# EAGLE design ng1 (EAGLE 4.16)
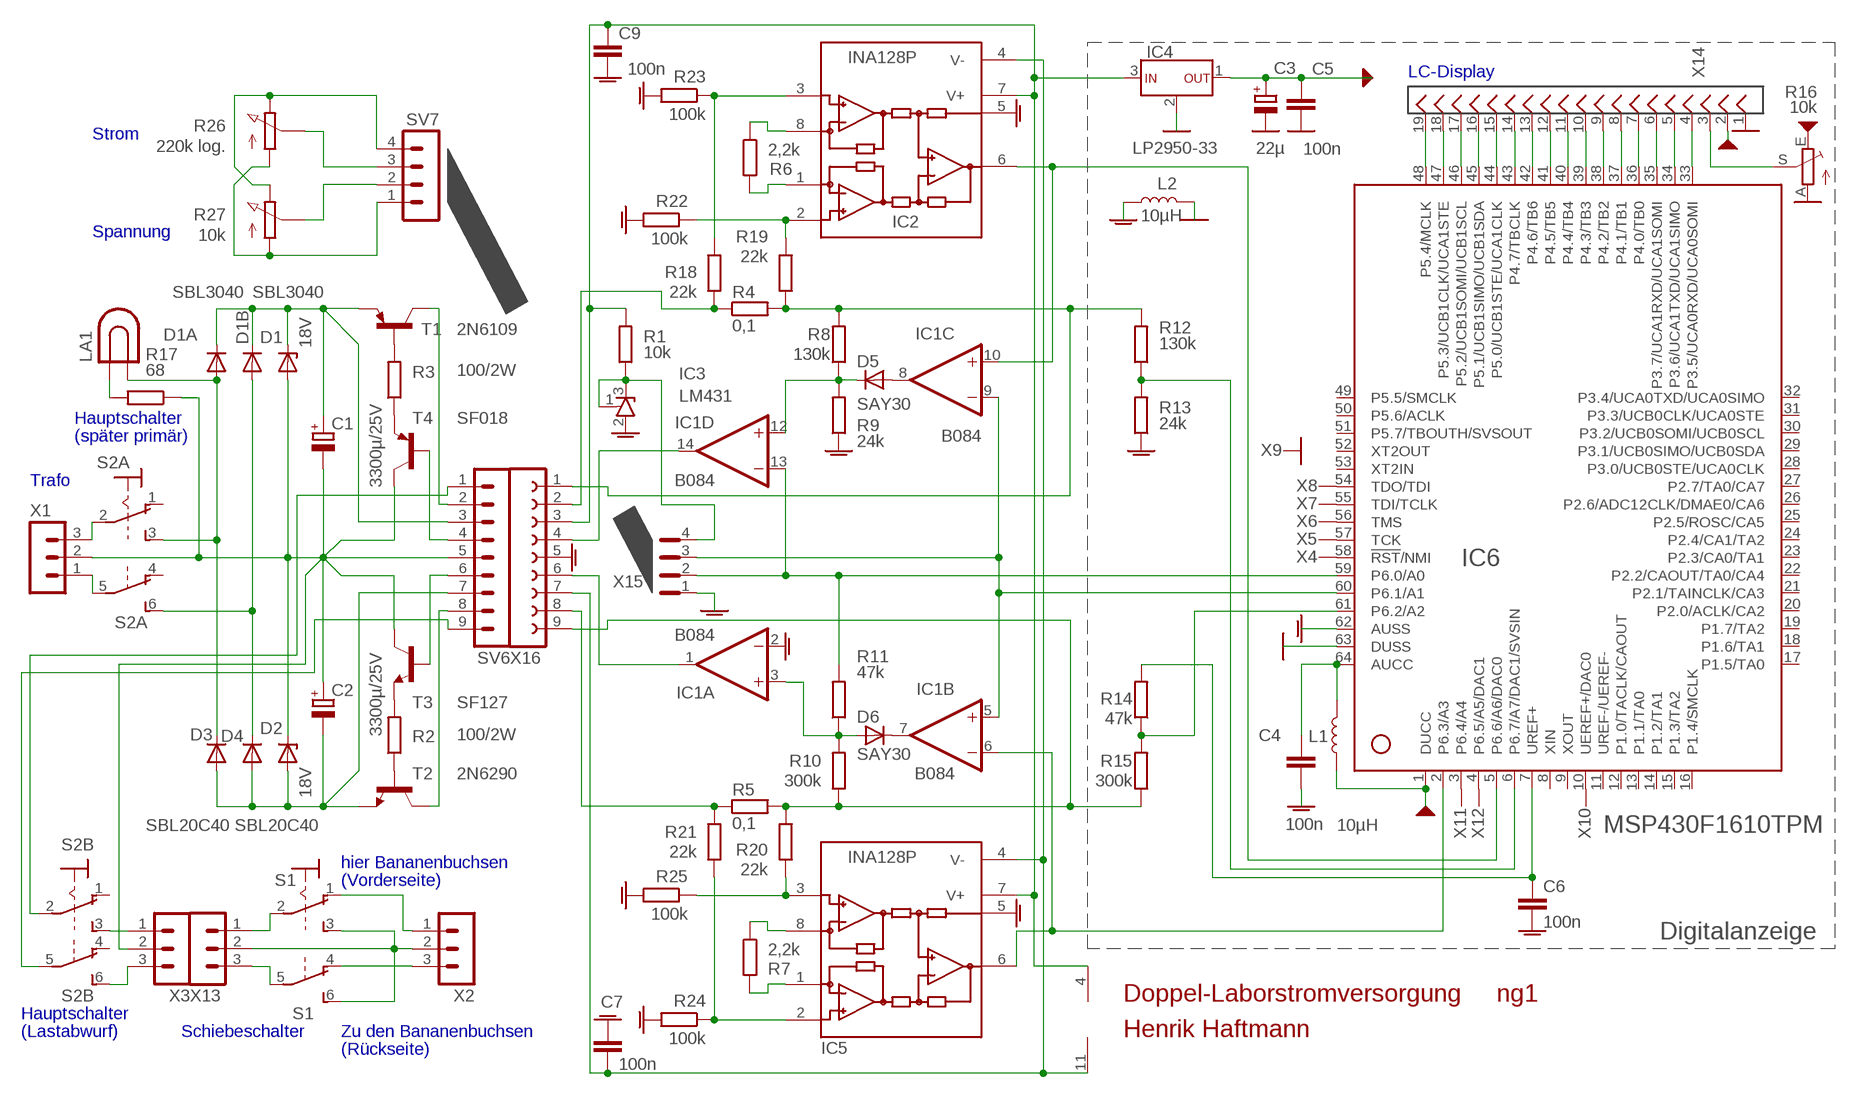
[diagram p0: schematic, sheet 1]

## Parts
C1  3300µ/25V  CPOL-EUE7.5-16  [E7,5-16]
C2  3300µ/25V  CPOL-EUE7.5-16  [E7,5-16]
C3  22µ  CPOL-EUE2-5  [E2-5]
C4  100n  C  [0603]
C5  100n  C  [0603]
C6  100n  C  [0603]
C7  100n  C-EU050-025X075  [C050-025X075]
C9  100n  C-EU050-025X075  [C050-025X075]
D1  18V  ZENER-DIODEC1702-15  [C1702-15]
D1A  SBL3040  DIODE  [DO202-17]
D1B  SBL3040  DIODE  [DO202-17]
D2  18V  ZENER-DIODEC1702-15  [C1702-15]
D3  SBL20C40  DIODE  [DO202-17]
D4  SBL20C40  DIODE  [DO202-17]
D5  SAY30  DD  [SAY]
D6  SAY30  DD  [SAY]
IC1  B084  TL084P  [DIL14]
IC2  INA128P  [DIL08]
IC3  LM431  TL431  [TO-92]
IC4  LP2950-33  78L05  [TO-92]
IC5  INA128P  [DIL08]
IC6  MSP430F1610TPM  MSP430F261TPM  [LQFP-64]
L1  10µH  L  [0603]
L2  10µH  L  [0603]
LA1  LAMP  [LDH-5R]
R1  10k  R-EU_0207/10  [0207/10]
R2  100/2W  R-EU_0617/22  [0617/22]
R3  100/2W  R-EU_0617/22  [0617/22]
R4  0,1  R-EU_0309/12  [0309/12]
R5  0,1  R-EU_0309/12  [0309/12]
R6  2,2k  R-EU_0207/10  [0207/10]
R7  2,2k  R-EU_0207/10  [0207/10]
R8  130k  R-EU_0207/10  [0207/10]
R9  24k  R-EU_0207/10  [0207/10]
R10  300k  R-EU_0207/10  [0207/10]
R11  47k  R-EU_0207/10  [0207/10]
R12  130k  R-EU_0207/10  [0207/10]
R13  24k  R-EU_0207/10  [0207/10]
R14  47k  R-EU_0207/10  [0207/10]
R15  300k  R-EU_0207/10  [0207/10]
R16  10k  TRIM_EU-CA9V  [CA9V]
R17  68  R-EU_0207/10  [0207/10]
R18  22k  R-EU_0207/10  [0207/10]
R19  22k  R-EU_0207/10  [0207/10]
R20  22k  R-EU_0207/10  [0207/10]
R21  22k  R-EU_0207/10  [0207/10]
R22  100k  R-EU_0207/10  [0207/10]
R23  100k  R-EU_0207/10  [0207/10]
R24  100k  R-EU_0207/10  [0207/10]
R25  100k  R-EU_0207/10  [0207/10]
R26  220k log.  PC25  [PC25]
R27  10k  PC25  [PC25]
S1  320-938  [320-938]
S2A  320-938  [320-938]
S2B  320-938  [320-938]
SV6  MA09-1  [MA09-1]
SV7  MA04-1  [MA04-1]
T1  2N6109  -PNP-TO220V  [TO220V]
T2  2N6290  -NPN-TO220V  [TO220V]
T3  SF127  -NPN-TO5  [TO5]
T4  SF018  -PNP-TO5  [TO5]
X1  MA03-1  [MA03-1]
X2  MA03-1  [MA03-1]
X3  MA03-1  [MA03-1]
X4  PADM  [SMD-1MM5]
X5  PADM  [SMD-1MM5]
X6  PADM  [SMD-1MM5]
X7  PADM  [SMD-1MM5]
X8  PADM  [SMD-1MM5]
X9  PADM  [SMD-1MM5]
X10  PADM  [SMD-1MM5]
X11  PADM  [SMD-1MM5]
X12  PADM  [SMD-1MM5]
X13  MA03-1  [MA03-1]
X14  FFC19  [FFC19]
X15  M4  [M4]
X16  FE09-1  [FE09]

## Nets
3P3: C3.+ C5.1 IC4.1(OUT) IC6.1(DUCC) L1.1 R16.E X14.2
15N: R5.2 R10.1 R15.1 R20.2 X16.9
15P: R4.2 R8.2 R12.2 R19.1 X16.1
18N: C7.2 IC1.11(P:V-) IC2.4(V-) IC5.4(V-) X16.7
18N1: C2.- D2.A D3.A D4.A SV6.7 T2.3(E)
18P: C9.1 IC1.4(P:V+) IC2.7(V+) IC4.3(IN) IC5.7(V+) R1.2 X16.3
18P1: C1.+ D1.C D1A.C D1B.C SV6.3 T1.3(E)
AGND: C4.2 C6.2 C7.1 C9.2 IC1.2(A:-IN) IC2.5(REF) IC3.2(A) IC5.5(REF) IC6.62(AUSS) L2.2 R9.1 R13.1 R22.2 R23.2 R24.2 R25.2 X15.1 X16.5
GND: C3.- C5.2 IC4.2(GND) IC6.63(DUSS) L2.1 R16.A X9.1 X14.1
GND1: C1.- C2.+ D1.A D2.C R17.1 SV6.5 T3.3(C) T4.3(C) X1.2 X3.2
N$1: D1A.A D3.C LA1.2 S2A.3(1:S)
N$2: D1B.A D4.C S2A.6(B:S)
N$3: IC6.46(P5.2/UCB1SOMI/UCB1SCL) X14.17
N$4: IC6.47(P5.3/UCB1CLK/UCA1STE) X14.18
N$5: IC6.48(P5.4/MCLK) X14.19
N$6: R2.1 T2.1(B)
N$7: R3.2 T1.1(B)
N$8: R3.1 T4.1(E)
N$9: R2.2 T3.1(E)
N$10: IC3.1(R) IC3.3(C) R1.1 X15.4
N$11: IC6.3(P6.4/A4) X11.1
N$12: R4.1 R18.1 X16.2
N$13: R5.1 R21.2 X16.8
N$14: IC6.4(P6.5/A5/DAC1) X12.1
N$15: IC2.8(RG) R6.1
N$16: IC2.1(RG) R6.2
N$17: LA1.1 R17.2
N$18: IC5.1(RG) R7.2
N$19: IC5.8(RG) R7.1
N$20: S2A.2(1:P) X1.3
N$22: D5.K IC1.12(D:+IN) R8.1 R9.2
N$23: D5.A IC1.8(C:OUT)
N$24: IC1.13(D:-IN) IC6.59(P6.0/A0) R11.2 X15.2
N$25: D6.A IC1.3(A:+IN) R10.2 R11.1
N$26: IC1.6(B:-IN) IC5.6(OUT) IC6.2(P6.3/A3)
N$27: IC1.10(C:+IN) IC2.6(OUT) IC6.5(P6.6/A6/DAC0)
N$28: IC1.5(B:+IN) IC1.9(C:-IN) IC6.60(P6.1/A1) X15.3
N$29: D6.K IC1.7(B:OUT)
N$30: IC6.6(P6.7/A7/DAC1/SVSIN) R12.1 R13.2
N$31: IC6.61(P6.2/A2) R14.1 R15.2
N$32: IC6.43(P4.7/TBCLK) X14.14
N$33: IC6.42(P4.6/TB6) X14.13
N$34: IC6.41(P4.5/TB5) X14.12
N$35: IC6.40(P4.4/TB4) X14.11
N$36: IC6.39(P4.3/TB3) X14.10
N$37: IC6.38(P4.2/TB2) X14.9
N$38: IC6.37(P4.1/TB1) X14.8
N$39: IC6.58(!RST!/NMI) X4.1
N$40: IC6.57(TCK) X5.1
N$41: IC6.56(TMS) X6.1
N$42: IC6.54(TDO/TDI) X8.1
N$43: IC6.55(TDI/TCLK) X7.1
N$44: C4.1 IC6.64(AUCC) L1.2
N$45: R16.S X14.3
N$46: IC6.10(UEREF+/DAC0) X10.1
N$49: C6.1 IC6.7(UREF+) R14.2
N$50: IC5.3(+IN) R20.1 R25.1
N$51: IC2.2(-IN) R19.2 R22.1
N$52: IC2.3(+IN) R18.2 R23.1
N$53: IC5.2(-IN) R21.1 R24.1
N$54: S2A.5(B:P) X1.1
N$55: SV6.6 T3.2(B)
N$56: SV6.4 T4.2(B)
N$57: SV6.8 T2.2(C)
N$58: SV6.2 T1.2(C)
N$59: IC1.14(D:OUT) X16.4
N$60: IC1.1(A:OUT) X16.6
N$61: R26.E R27.E SV7.4
N$62: R26.S SV7.3
N$63: R27.S SV7.2
N$64: R26.A R27.A SV7.1
N$65: S1.2(1:P) X13.1
N$66: S2B.3(1:S) X3.1
N$67: S1.3(1:S) S1.6(B:S) X2.2 X13.2
N$68: S1.1(1:O) X2.1
N$69: S1.4(B:O) X2.3
N$70: S1.5(B:P) X13.3
N$71: S2B.6(B:S) X3.3
N$72: S2B.2(1:P) SV6.1
N$73: S2B.5(B:P) SV6.9
N$74: IC6.36(P4.0/TB0) X14.7
N$75: IC6.35(P3.7/UCA1RXD/UCA1SOMI) X14.6
N$76: IC6.34(P3.6/UCA1TXD/UCA1SIMO) X14.5
N$77: IC6.33(P3.5/UCA0RXD/UCA0SOMI) X14.4
N$79: IC6.44(P5.0/UCB1STE/UCA1CLK) X14.15
N$80: IC6.45(P5.1/UCB1SIMO/UCB1SDA) X14.16
Unconnected: IC6.8(XIN) IC6.9(XOUT) IC6.11(UREF-/UEREF-) IC6.12(P1.0/TACLK/CAOUT) IC6.13(P1.1/TA0) IC6.14(P1.2/TA1) IC6.15(P1.3/TA2) IC6.16(P1.4/SMCLK) IC6.17(P1.5/TA0) IC6.18(P1.6/TA1) IC6.19(P1.7/TA2) IC6.20(P2.0/ACLK/CA2) IC6.21(P2.1/TAINCLK/CA3) IC6.22(P2.2/CAOUT/TA0/CA4) IC6.23(P2.3/CA0/TA1) IC6.24(P2.4/CA1/TA2) IC6.25(P2.5/ROSC/CA5) IC6.26(P2.6/ADC12CLK/DMAE0/CA6) IC6.27(P2.7/TA0/CA7) IC6.28(P3.0/UCB0STE/UCA0CLK) IC6.29(P3.1/UCB0SIMO/UCB0SDA) IC6.30(P3.2/UCB0SOMI/UCB0SCL) IC6.31(P3.3/UCB0CLK/UCA0STE) IC6.32(P3.4/UCA0TXD/UCA0SIMO) IC6.49(P5.5/SMCLK) IC6.50(P5.6/ACLK) IC6.51(P5.7/TBOUTH/SVSOUT) IC6.52(XT2OUT) IC6.53(XT2IN) S2A.1(1:O) S2A.4(B:O) S2B.1(1:O) S2B.4(B:O)

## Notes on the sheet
- LC-Display
- Strom
- Spannung
- Hauptschalter
- (später primär)
- Trafo
- hier Bananenbuchsen
- (Vorderseite)
- Digitalanzeige
- Doppel-Laborstromversorgung
- Hauptschalter
- (Lastabwurf) | Schiebeschalter | Zu den Bananenbuchsen | Henrik Haftmann
- (Rückseite)

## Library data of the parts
C1-C3 = rcl:CPOL-EU: POLARIZED CAPACITOR, European symbol
C4-C6 = sm:C: Kondensator
C7 C9 = rcl:C-EU: CAPACITOR, European symbol
D1 D2 = diode:ZENER-DIODE: Z-Diode
D1A D1B D3 D4 = lm:DIODE: Diode
D5 D6 = sm:D: Diode
IC1 = linear:TL084: OP AMP
IC2 IC5 = burr-brown:INA128: Instrumentation Amplifiers Precision, Low Power
IC3 = lm:TL431*: Einstellbare Z-Diode Umin = 2,5 V
IC4 = lm:78L*: Spannungsregler
IC6 = sm:MSP430F261*TPM: Microcontroller 16 bit RISC 1.8 .. 3.6 V 16 MHz Low-Power 365 µA @ 1 MHz & 2.2 V, 0.5 µA Standby, 0.1 A Off, Wake-Up: 1 µs 40 I/O pins 3-channel DMA, 2 12-bit DAC (261x only) 1 12-bit ADC 2 16-bit timers with 3+7 capture/compare registers 4 universal serial interfaces (RS232, I²C, SPI, ...)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
L1 L2 = sm:L: Spule (Hochfrequenz)
LA1 = special:LAMP: LED HOLDER
R1-R15 R17-R25 = rcl:R-EU_: RESISTOR, European symbol
R16 = pot:TRIM_EU-: POTENTIOMETER
R26 R27 = pot-vitrohm:PC25: VITROHM POTENTIOMETER
S1 S2A S2B = switch:320-938: TOGGLE SWITCH distributor RS Components
SV6 = con-lstb:MA09-1: PIN HEADER
SV7 = con-lstb:MA04-1: PIN HEADER
T1 T4 = transistor:*-PNP-: PNP Transistror
T2 T3 = transistor:*-NPN-: NPN Transistror
X1-X3 X13 = con-lstb:MA03-1: PIN HEADER
X4-X12 = sm:PAD: Einfaches Lötpad
X14 = lm:FFC19: Flachkabel-Verbinder 19-polig
X15 = lm:M4: Stecker 4-pol.
X16 = con-lsta:FE09-1: FEMALE HEADER

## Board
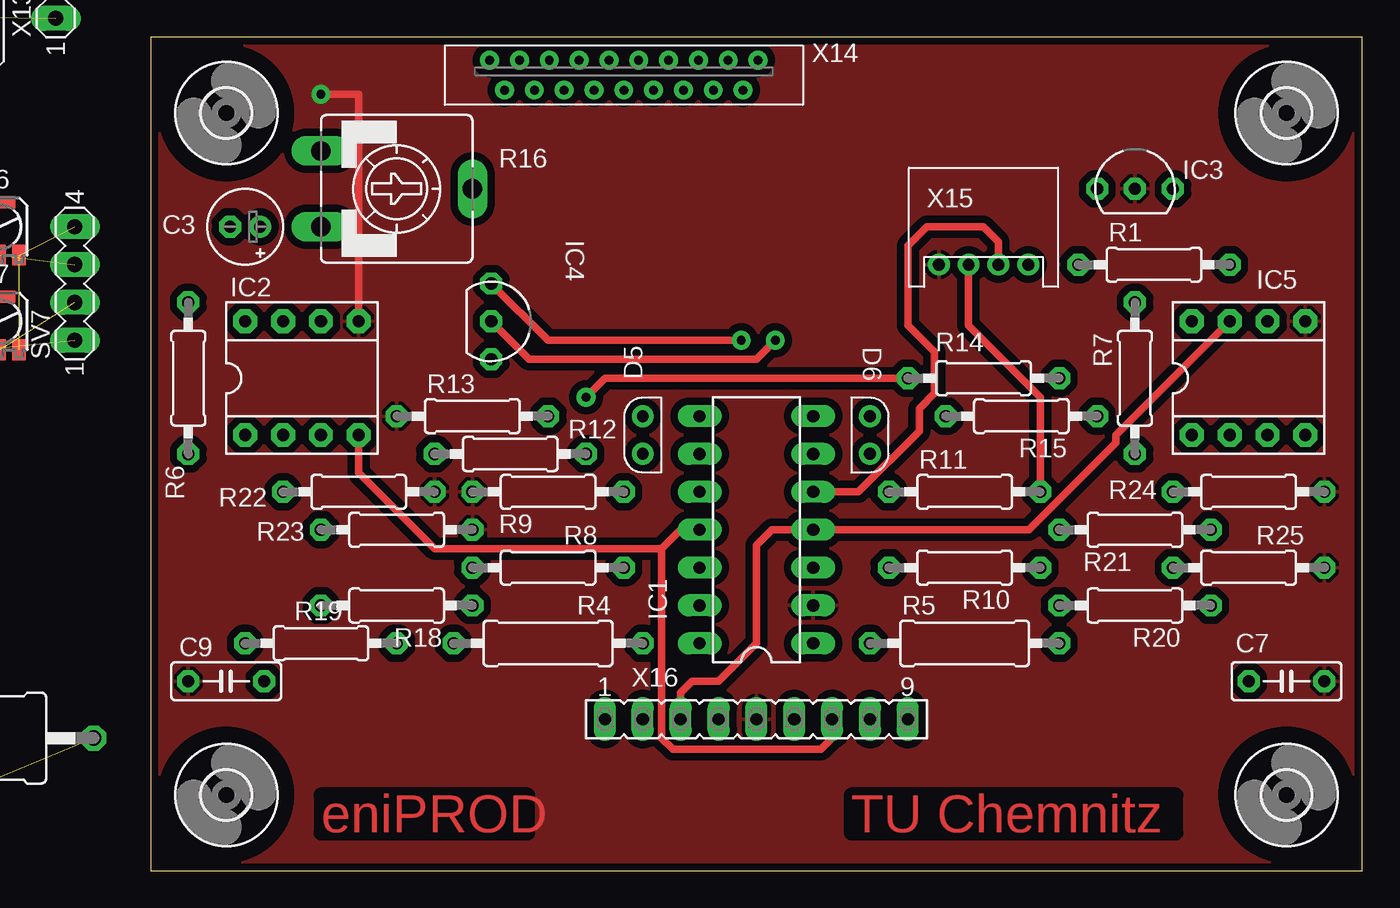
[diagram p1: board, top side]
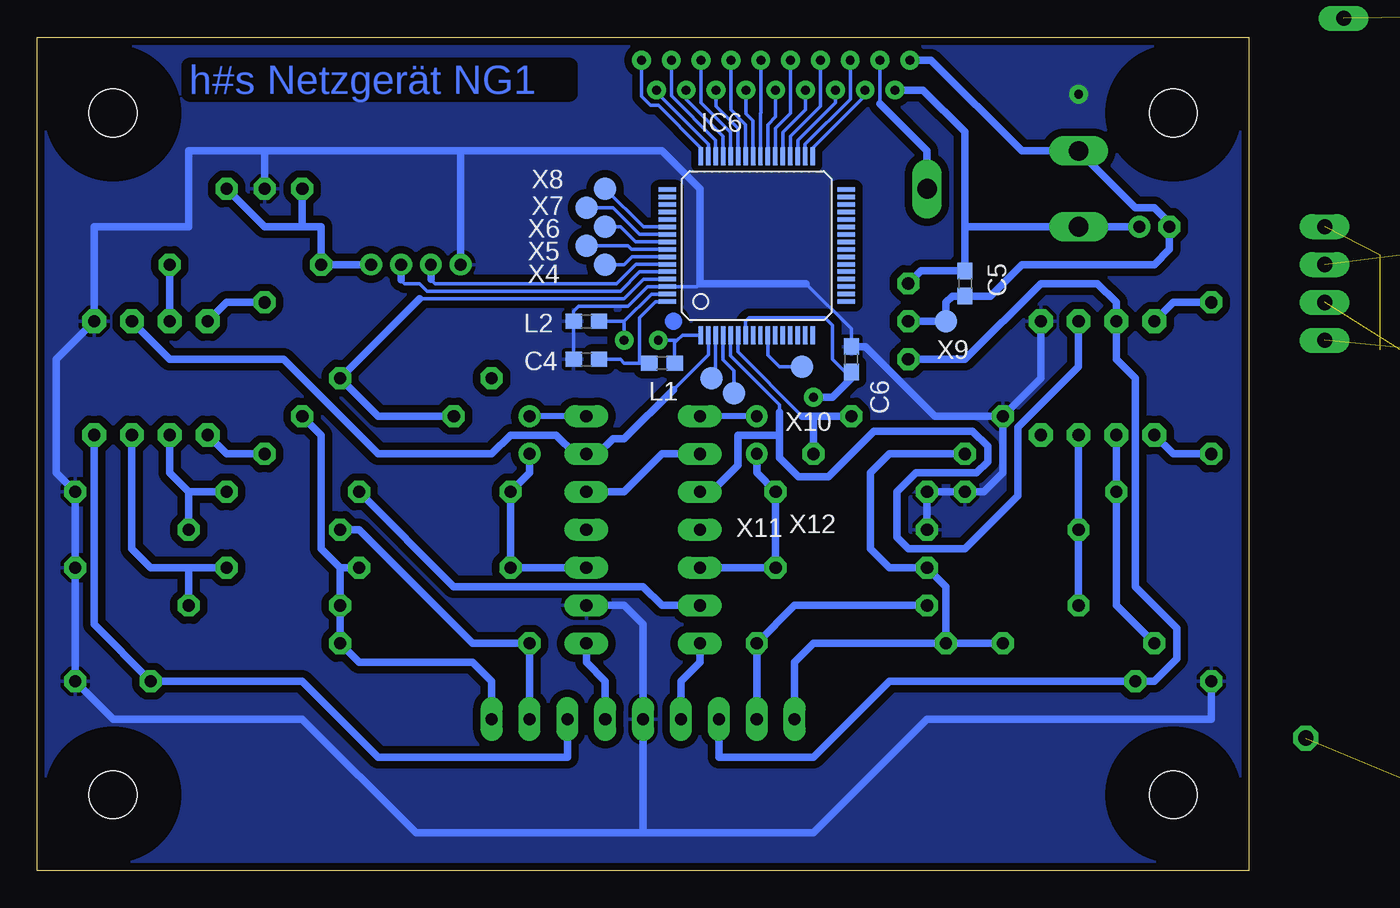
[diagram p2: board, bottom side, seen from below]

Size 81.28 x 55.88 mm. Coordinates in mm from the lower left corner, seen from the top.
Outline: 0,0 81.28,0 81.28,55.88 0,55.88 0,0
Copper layers (1*16): Top 0.035mm / dielectric 1.5mm / Bottom 0.035mm
Design rules "Felber": minimum track width 0.2mm, minimum drill 0.3mm, track to track 0.2mm, track to pad 0.2mm, pad to pad 0.2mm, via to via 0.2mm, smd to smd 0mil, copper to edge 0.3mm, drill to drill 0.3mm, minimum pad ring 13mil, minimum via ring 13mil, stop-mask expansion 4mil, vias tented up to drill 0.4mm, thermal gap 10mil

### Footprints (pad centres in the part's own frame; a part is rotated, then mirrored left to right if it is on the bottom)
E7,5-16 = drill 1.016 pad 3.15 round: + -3.81,0 | drill 1.016 pad 3.15 octagon: - 3.81,0
E2-5 = drill 0.813 pad 1.27 round: + -1.016,0 | drill 0.813 pad 1.27 octagon: - 1.016,0
0603 = smd 1.1 x 1: 1 -0.85,0; 2 0.85,0
C050-025X075 = drill 0.813 octagon: 1 -2.54,0; 2 2.54,0
C1702-15 = drill 1.397 long: A 7.62,0; C -7.62,0
DO202-17 = drill 1.499 round: A 7.62,0; C -7.62,0
SAY = drill 0.8 round: A 1.25,0; K -1.25,0
DIL14 = drill 0.813 long: 1 -7.62,-3.81; 2 -5.08,-3.81; 3 -2.54,-3.81; 4 0,-3.81; 5 2.54,-3.81; 6 5.08,-3.81; 7 7.62,-3.81; 8 7.62,3.81; 9 5.08,3.81; 10 2.54,3.81; 11 0,3.81; 12 -2.54,3.81; 13 -5.08,3.81; 14 -7.62,3.81
DIL08 = drill 0.813 pad 1.6 octagon: 1 -3.81,-3.81; 2 -1.27,-3.81; 3 1.27,-3.81; 4 3.81,-3.81; 5 3.81,3.81; 6 1.27,3.81; 7 -1.27,3.81; 8 -3.81,3.81
TO-92 = drill 0.813 octagon: 1 -2.54,0; 2 0,0; 3 2.54,0
LQFP-64 = smd 0.3 x 1.2: 1 -3.75,-6; 2 -3.25,-6; 3 -2.75,-6; 4 -2.25,-6; 5 -1.75,-6; 6 -1.25,-6; 7 -0.75,-6; 8 -0.25,-6; 9 0.25,-6; 10 0.75,-6; 11 1.25,-6; 12 1.75,-6; 13 2.25,-6; 14 2.75,-6; 15 3.25,-6; 16 3.75,-6; 33 3.75,6; 34 3.25,6; 35 2.75,6; 36 2.25,6; 37 1.75,6; 38 1.25,6; 39 0.75,6; 40 0.25,6; 41 -0.25,6; 42 -0.75,6; 43 -1.25,6; 44 -1.75,6; 45 -2.25,6; 46 -2.75,6; 47 -3.25,6; 48 -3.75,6 | smd 1.2 x 0.3: 17 6,-3.75; 18 6,-3.25; 19 6,-2.75; 20 6,-2.25; 21 6,-1.75; 22 6,-1.25; 23 6,-0.75; 24 6,-0.25; 25 6,0.25; 26 6,0.75; 27 6,1.25; 28 6,1.75; 29 6,2.25; 30 6,2.75; 31 6,3.25; 32 6,3.75; 49 -6,3.75; 50 -6,3.25; 51 -6,2.75; 52 -6,2.25; 53 -6,1.75; 54 -6,1.25; 55 -6,0.75; 56 -6,0.25; 57 -6,-0.25; 58 -6,-0.75; 59 -6,-1.25; 60 -6,-1.75; 61 -6,-2.25; 62 -6,-2.75; 63 -6,-3.25; 64 -6,-3.75
LDH-5R = drill 0.813 long: 1 -1.27,-5.08; 2 1.27,-5.08 | hole 1.219: 2.54,0; -2.54,0
0207/10 = drill 0.813 octagon: 1 -5.08,0; 2 5.08,0
0617/22 = drill 1.016 octagon: 1 -11.43,0; 2 11.43,0
0309/12 = drill 0.813 octagon: 1 -6.35,0; 2 6.35,0
CA9V = drill 1.321 long: A -2.54,-5.08; E 2.54,-5.08; S 0,5.08
PC25 = smd 2.2 x 0.8: 4 0,1.65 | smd 0.9 x 1.4: A -1.35,-1.9; E 1.35,-1.9; S 0,-1.9
320-938 = drill 2.007 octagon: 1 -2.388,4.013; 2 -2.388,0; 3 -2.388,-4.013; 4 2.388,4.013; 5 2.388,0; 6 2.388,-4.013
MA09-1 = drill 1.016 long: 1 -10.16,0; 2 -7.62,0; 3 -5.08,0; 4 -2.54,0; 5 0,0; 6 2.54,0; 7 5.08,0; 8 7.62,0; 9 10.16,0
MA04-1 = drill 1.016 long: 1 -3.81,0; 2 -1.27,0; 3 1.27,0; 4 3.81,0
TO220V = drill 1.016 long: 1 -2.54,-2.54; 2 0,-2.54; 3 2.54,-2.54
TO5 = drill 0.813 octagon: 1 0,-2.54; 2 2.54,0; 3 0,2.54
3,2 = hole 3.2: 0,0
MA03-1 = drill 1.016 long: 1 -2.54,0; 2 0,0; 3 2.54,0
SMD-1MM5 = smd 1.5 x 1.5: 1 0,0
FFC19 = drill 0.6 round: 1 -9,1; 2 -8,-1; 3 -7,1; 4 -6,-1; 5 -5,1; 6 -4,-1; 7 -3,1; 8 -2,-1; 9 -1,1; 10 0,-1; 11 1,1; 12 2,-1; 13 3,1; 14 4,-1; 15 5,1; 16 6,-1; 17 7,1; 18 8,-1; 19 9,1
M4 = drill 0.8 round: 1 -3,0; 2 -1,0; 3 1,0; 4 3,0
FE09 = drill 0.813 long: 1 -10.16,0; 2 -7.62,0; 3 -5.08,0; 4 -2.54,0; 5 0,0; 6 2.54,0; 7 5.08,0; 8 7.62,0; 9 10.16,0

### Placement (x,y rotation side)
C1  not placed on the board
C2  not placed on the board
C3  6.35,43.18 180 top
C4  44.45,34.29 180 bottom
C5  19.05,39.37 270 bottom
C6  26.67,34.29 90 bottom
C7  76.2,12.7 180 top
C9  5.08,12.7 180 top
D1  not placed on the board
D1A  not placed on the board
D1B  not placed on the board
D2  not placed on the board
D3  not placed on the board
D4  not placed on the board
D5  33.02,29.21 90 top
D6  48.26,29.21 270 top
IC1  40.64,22.86 90 top
IC2  10.16,33.02 0 top
IC3  66.04,45.72 0 top
IC4  22.86,36.83 270 top
IC5  73.66,33.02 0 top
IC6  33.02,41.91 0 bottom
L1  39.37,34.04 180 bottom
L2  44.45,36.83 180 bottom
LA1  not placed on the board
R1  67.31,40.64 0 top
R2  not placed on the board
R3  not placed on the board
R4  26.67,15.24 180 top
R5  54.61,15.24 0 top
R6  2.54,33.02 270 top
R7  66.04,33.02 270 top
R8  26.67,20.32 180 top
R9  26.67,25.4 0 top
R10  54.61,20.32 180 top
R11  54.61,25.4 0 top
R12  24.13,27.94 180 top
R13  21.59,30.48 0 top
R14  55.88,33.02 180 top
R15  58.42,30.48 180 top
R16  16.51,45.72 270 top
R17  not placed on the board
R18  16.51,17.78 180 top
R19  11.43,15.24 180 top
R20  66.04,17.78 180 top
R21  66.04,22.86 180 top
R22  13.97,25.4 0 top
R23  16.51,22.86 0 top
R24  73.66,25.4 0 top
R25  73.66,20.32 0 top
R26  not placed on the board
R27  not placed on the board
S1  not placed on the board
S2A  not placed on the board
S2B  not placed on the board
SV6  not placed on the board
SV7  not placed on the board
T1  not placed on the board
T2  not placed on the board
T3  not placed on the board
T4  not placed on the board
U$1  [3,2]  5.08,5.08 0 top
U$2  [3,2]  76.2,5.08 0 top
U$3  [3,2]  76.2,50.8 0 top
U$4  [3,2]  5.08,50.8 0 top
X1  not placed on the board
X2  not placed on the board
X3  not placed on the board
X4  43.18,40.64 0 bottom
X5  44.45,41.91 0 bottom
X6  43.18,43.18 0 bottom
X7  44.45,44.45 0 bottom
X8  43.18,45.72 0 bottom
X9  20.32,36.83 0 bottom
X10  29.97,33.78 0 bottom
X11  36.07,33.02 0 bottom
X12  34.54,32 0 bottom
X13  not placed on the board
X14  31.75,53.34 0 top
X15  55.88,40.64 0 top
X16  40.64,10.16 0 top

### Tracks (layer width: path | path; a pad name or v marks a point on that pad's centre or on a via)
3P3  (via drill 0.6)
  Top 0.5: v39.62,35.56 26.67,35.56 IC4.1
  Bottom 0.25: IC6.1 38,35.91 38.35,35.56 | L1.1 38.52,35.39 38.35,35.56 | v39.62,35.56 38.35,35.56
  Bottom 0.5: X14.2 21.86,52.34 19.05,49.53 19.05,43.18 | C3.+ R16.E 19.05,43.18 | IC4.1 22.01,40.22 C5.1 19.05,43.18
15N
  Bottom 0.5: X16.9 50.8,12.7 52.07,13.97 59.69,13.97 R5.2 R20.2 60.96,20.32 | 60.96,20.32 R10.1 | R15.1 62.23,29.21 62.23,21.59 60.96,20.32
15P
  Bottom 0.5: X16.1 30.48,13.97 29.21,15.24 R4.2 | R12.2 24.13,27.94 25.4,26.67 25.4,21.59 24.13,20.32 R8.2 20.32,19.05 R4.2 | R19.1 R4.2
18N
  Top 0.5: IC2.4 13.97,26.67 19.05,21.59 34.29,21.59 | 34.29,21.59 35.56,22.86 IC1.11 | 34.29,21.59 34.29,8.89 35.05,8.13 44.96,8.13 45.72,8.89 X16.7
  Bottom 0.5: IC5.4 77.47,16.51 C7.2 63.5,12.7 58.42,7.62 45.72,7.62 X16.7
18N1  (5 unrouted)
18P
  Top 0.5: IC5.7 64.77,29.21 64.77,28.7 58.93,22.86 IC1.4 41.69,22.86 40.64,21.81 40.64,15.24 38.1,12.7 36.32,12.7 35.56,11.94 X16.3
  Bottom 0.5: IC5.7 R1.2 | X16.3 35.56,7.62 29.21,7.62 24.13,12.7 C9.1 6.35,12.7 4.83,14.22 4.83,16.26 7.62,19.05 7.62,33.02 8.89,34.29 IC2.7 8.89,38.1 10.16,39.37 13.97,39.37 19.05,34.29 IC4.3
18P1  (5 unrouted)
AGND  (via drill 0.6)
  Top 0.5: IC2.5 13.97,52.07 v11.43,52.07
  Bottom 0.25: 36.83,39.37 37.04,39.16 IC6.62 40.34,39.16 41.66,37.85 44.96,37.85 45.3,37.5 L2.2 C4.2 | C6.2 26.67,36.32 29.72,39.37
  Bottom 0.5: IC1.2 41.91,17.78 40.64,16.51 X16.5 40.64,2.54 | 40.64,2.54 55.88,2.54 63.5,10.16 76.2,10.16 C7.1 R25.2 R24.2 80.01,26.67 80.01,34.29 IC5.5 77.47,43.18 71.12,43.18 71.12,48.26 66.04,48.26 | 52.88,48.26 X15.1 | 66.04,48.26 52.88,48.26 | 66.04,48.26 IC3.2 | 40.64,2.54 29.21,2.54 21.59,10.16 2.54,10.16 C9.2 | R23.2 R9.1 R22.2 17.78,25.4 16.51,26.67 R13.1 | 52.88,48.26 39.37,48.26 36.83,45.72 36.83,39.37 29.72,39.37 | IC2.5 13.97,33.02 R13.1 | C6.2 25.74,35.14 21.08,30.48 R13.1
  pour Bottom (isolate 0.5): 0,55.88 81.28,55.88 81.28,0 0,0
  pour Top (isolate 0.5): 0,55.88 81.28,55.88 81.28,0 0,0
GND  (via drill 0.6)
  Top 0.5: v41.91,35.56 40.64,34.29 25.4,34.29 IC4.2
  Bottom 0.25: IC6.63 40.08,38.66 41.91,36.83 | 41.91,36.83 L2.1 | v41.91,35.56 41.91,36.83
  Bottom 0.5: IC4.2 X9.1 20.32,38.1 19.9,38.52 C5.2 17.36,38.52 15.24,40.64 6.35,40.64 5.33,41.66 C3.- 5.33,43.43 6.35,44.45 7.62,44.45 R16.A 15.24,48.26 21.32,54.34 X14.1
GND1  (9 unrouted)
N$1  (3 unrouted)
N$2  (2 unrouted)
N$3
  Bottom 0.25: IC6.46 35.77,48.98 38.75,51.96 X14.17
N$4
  Bottom 0.25: IC6.47 36.27,48.72 39.75,52.2 X14.18
N$5
  Bottom 0.25: IC6.48 36.77,48.45 39.62,51.31 40.13,51.31 40.75,51.93 X14.19
N$6  (1 unrouted)
N$7  (1 unrouted)
N$8  (1 unrouted)
N$9  (1 unrouted)
N$10
  Bottom 0.5: IC3.3 66.04,43.18 63.5,43.18 | 63.5,43.18 IC3.1 | 63.5,43.18 62.23,43.18 R1.1 X15.4
N$11
  Bottom 0.25: IC6.3 35.77,33.32 X11.1
N$12
  Bottom 0.5: X16.2 R4.1 30.48,17.78 R18.1
N$13
  Bottom 0.5: X16.8 R5.1 52.07,15.24 59.69,22.86 R21.2
N$14
  Bottom 0.25: IC6.4 35.27,34.25 34.54,33.53 X12.1
N$15
  Bottom 0.5: R6.1 5.08,38.1 IC2.8
N$16
  Bottom 0.5: R6.2 5.08,27.94 IC2.1
N$17  (1 unrouted)
N$18
  Bottom 0.5: R7.2 68.58,27.94 IC5.1
N$19
  Bottom 0.5: R7.1 68.58,38.1 IC5.8
N$20  (1 unrouted)
N$22
  Bottom 0.5: D5.K 33.02,26.67 R9.2 R8.1 IC1.12
N$23
  Bottom 0.406: D5.A 36.83,30.46 IC1.8
N$24
  Top 0.5: X15.2 54.88,36.56 59.69,31.75 R11.2
  Bottom 0.25: IC6.59 41.13,40.66 42.42,39.37 54.61,39.37 54.88,39.64
  Bottom 0.5: X15.2 54.88,39.64 | IC1.13 39.37,17.78 40.64,19.05 53.34,19.05 R11.2
N$25
  Bottom 0.5: IC1.3 R10.2 R11.1 48.26,26.67 D6.A
N$26
  Bottom 0.25: IC6.2 36.27,34.6 38.61,32.26
  Bottom 0.5: 38.61,32.26 41.91,28.96 42.67,28.96 43.69,27.94 IC1.6 45.21,27.94 46.48,29.21 49.53,29.21 50.8,27.94 58.42,27.94 64.77,34.29 72.39,34.29 IC5.6
N$27
  Bottom 0.25: IC6.5 34.77,34.52 31.5,31.24 31.5,30.73
  Bottom 0.5: 31.5,29.21 31.5,30.73 | 31.5,29.21 34.29,29.21 34.29,27.18 36.07,25.4 IC1.10 | IC2.6 11.43,33.78 15.49,29.72 15.49,25.15 19.05,21.59 22.86,21.59 23.62,22.35 23.62,25.4 22.35,26.67 18.29,26.67 17.53,27.43 17.53,28.45 18.54,29.46 25.15,29.46 28.19,26.42 30.23,26.42 31.5,27.69 31.5,29.21
N$28
  Top 0.5: IC1.5 47.5,25.4 51.56,29.46 51.56,30.99 52.58,32 52.58,34.8 50.8,36.58 50.8,41.91 52.07,43.18 55.88,43.18 56.88,42.18 X15.3
  Bottom 0.25: IC6.60 40.87,40.16 42.16,38.86 55.12,38.86 55.63,39.37 56.64,39.37 56.88,39.61
  Bottom 0.5: IC1.9 39.37,27.94 41.91,25.4 IC1.5 | X15.3 56.88,39.61
N$29
  Bottom 0.406: D6.K 48.26,30.48 IC1.7
N$30
  Bottom 0.25: IC6.6 34.27,34.78 29.97,30.48
  Bottom 0.5: R13.2 29.21,30.48 | 29.21,30.48 29.97,30.48 | 29.21,30.48 R12.1
N$31
  Bottom 0.25: IC6.61 40.6,39.66 41.91,38.35 55.63,38.35
  Bottom 0.5: 55.63,38.35 R14.1 58.42,30.48 R15.2
N$32
  Bottom 0.25: IC6.43 34.27,49.76 35.75,51.24 X14.14
N$33
  Bottom 0.25: IC6.42 33.77,50.03 34.75,51.01 X14.13
N$34
  Bottom 0.25: IC6.41 33.27,50.29 33.75,50.77 X14.12
N$35
  Bottom 0.25: X14.11 32.75,50.82 32.77,50.8 IC6.40
N$36
  Bottom 0.25: X14.10 31.75,50.55 32.27,50.03 IC6.39
N$37
  Bottom 0.25: X14.9 30.75,50.78 31.77,49.76 IC6.38
N$38
  Bottom 0.25: X14.8 29.75,51.02 31.27,49.5 IC6.37
N$39
  Bottom 0.25: IC6.58 41.39,41.16 41.91,40.64 X4.1
N$40
  Bottom 0.25: IC6.57 41.41,41.66 41.66,41.91 X5.1
N$41
  Bottom 0.25: IC6.56 41.14,42.16 42.16,43.18 X6.1
N$42
  Bottom 0.25: IC6.54 40.62,43.16 X8.1
N$43
  Bottom 0.25: IC6.55 40.88,42.66 42.67,44.45 X7.1
N$44
  Bottom 0.25: IC6.64 39.82,38.16 40.89,37.08 40.89,34.04 | 40.89,34.04 41.91,34.04 42.16,34.29 C4.1 | L1.2 40.89,34.04
N$45
  Bottom 0.25: 24.75,51.42 X14.3
  Bottom 0.5: 24.75,51.42 24.13,50.8 21.59,48.26 R16.S
N$46
  Bottom 0.25: IC6.10 32.27,34.56 31.5,33.78 X10.1
N$49  (via drill 0.6)
  Top 0.5: R14.2 30.48,33.02 v29.21,31.75
  Bottom 0.25: IC6.7 33.77,36.84 33.53,37.08 28.45,37.08 27.94,36.58 27.94,34.29 27.09,33.44 C6.1 26.67,33.02
  Bottom 0.5: v29.21,31.75 27.94,31.75 26.67,33.02
N$50
  Bottom 0.5: IC5.3 74.93,21.59 73.66,20.32 71.12,20.32 | R25.1 71.12,20.32 | 71.12,20.32 R20.1
N$51
  Bottom 0.5: IC2.2 R22.1 8.89,17.78 R19.2
N$52
  Bottom 0.5: R18.2 R23.1 IC2.3
N$53
  Bottom 0.5: R24.1 71.12,25.4 | 71.12,25.4 72.39,26.67 IC5.2 | 71.12,25.4 R21.1
N$54  (1 unrouted)
N$55  (1 unrouted)
N$56  (1 unrouted)
N$57  (1 unrouted)
N$58  (1 unrouted)
N$59
  Bottom 0.5: IC1.14 36.83,13.97 38.1,12.7 X16.4
N$60
  Bottom 0.5: IC1.1 44.45,13.97 43.18,12.7 X16.6
N$61  (2 unrouted)
N$62  (1 unrouted)
N$63  (1 unrouted)
N$64  (2 unrouted)
N$65  (1 unrouted)
N$66  (1 unrouted)
N$67  (3 unrouted)
N$68  (1 unrouted)
N$69  (1 unrouted)
N$70  (1 unrouted)
N$71  (1 unrouted)
N$72  (1 unrouted)
N$73  (1 unrouted)
N$74
  Bottom 0.25: X14.7 28.75,51.26 30.77,49.24 IC6.36
N$75
  Bottom 0.25: X14.6 27.75,51.5 30.27,48.98 IC6.35
N$76
  Bottom 0.25: X14.5 26.75,51.74 29.77,48.72 IC6.34
N$77
  Bottom 0.25: X14.4 25.75,51.97 29.27,48.45 IC6.33
N$79
  Bottom 0.25: IC6.44 34.77,49.5 36.75,51.48 X14.15
N$80
  Bottom 0.25: IC6.45 35.27,49.24 37.75,51.72 X14.16
(copper drawn outside any net)
  shapes: Bottom circle x1

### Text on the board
Top: eniPROD | TU Chemnitz
Bottom: h#s Netzgerät NG1
Measures: 56 | 81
